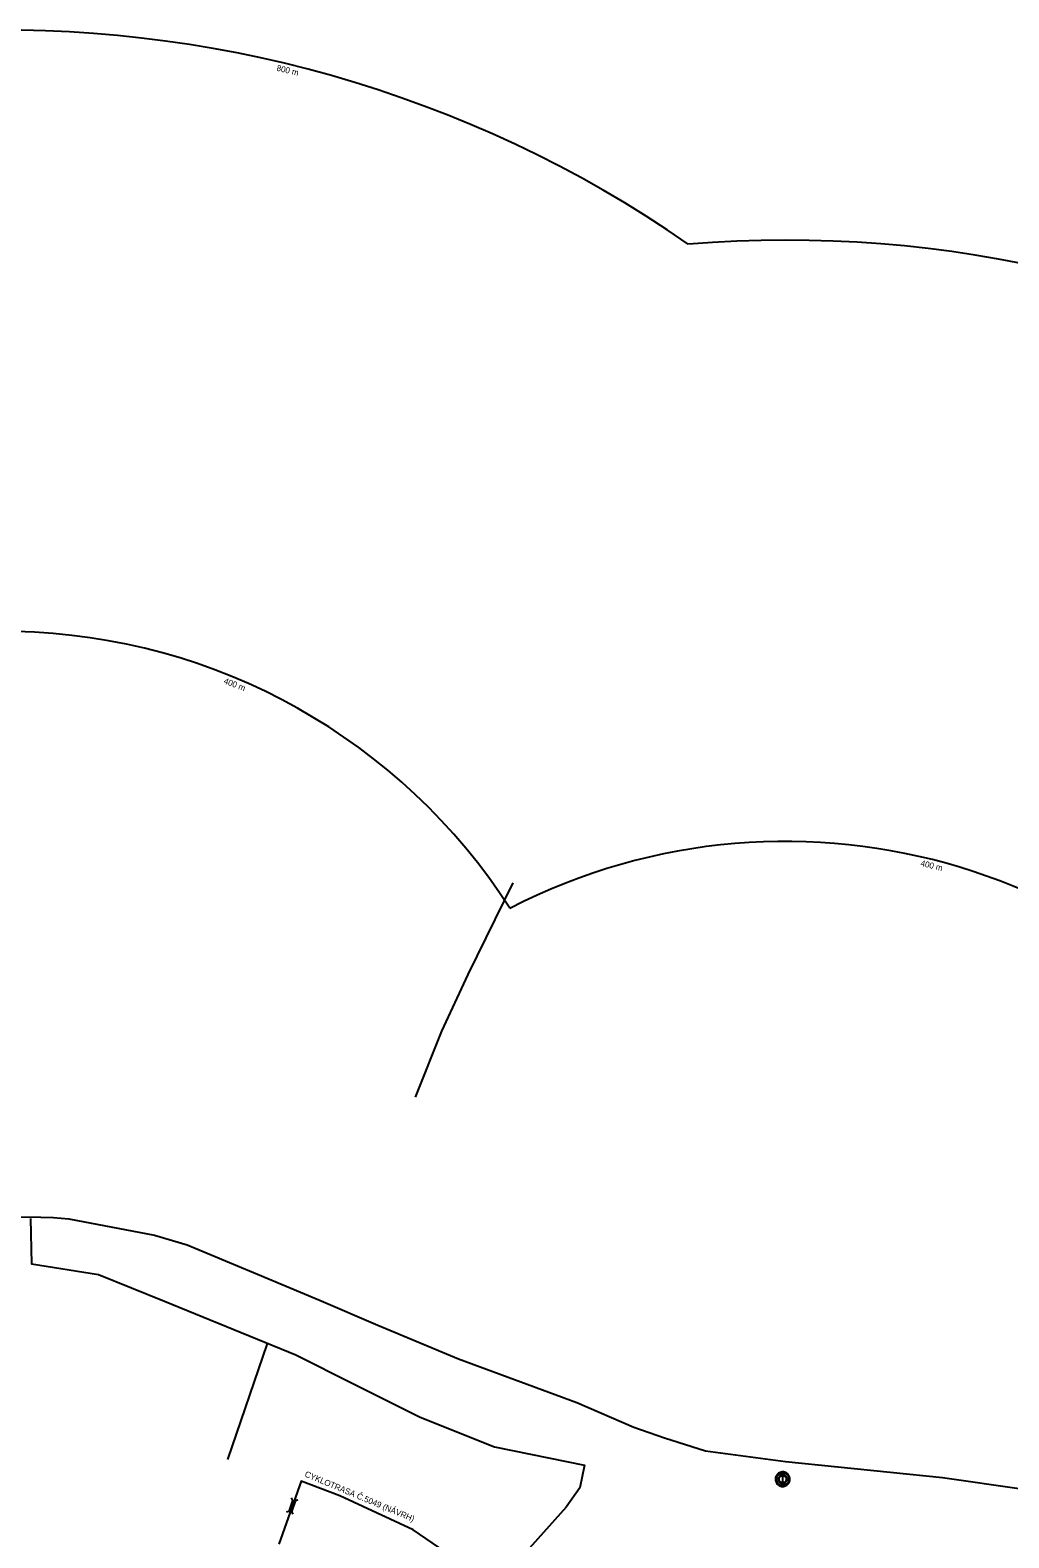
# Model space of a CAD drawing. Extents: x -520790 to -517278, y -1190021 to -1185077.
# Drawn here: x -518752 to -518101, y -1187379 to -1186376 of the extents above; entities that cross this region are included whole.
import ezdxf

# ---------------------------------------------------------------- set-up
doc = ezdxf.new("R2010")
doc.units = 0
for name, color, linetype in [('cyklostezka_n', 7, 'Continuous'), ('cyklostezka_s', 7, 'Continuous'), ('dostupnost_s', 7, 'Continuous'), ('most_s', 7, 'Continuous'), ('stezka_s', 7, 'Continuous'), ('zast_HD_s', 7, 'Continuous')]:
    doc.layers.add(name, color=color, linetype=linetype)

msp = doc.modelspace()

# ---------------------------------------------------------------- linework, layer by layer
at = {"layer": 'cyklostezka_n'}
msp.add_lwpolyline([(-518752, -1187166.7), (-518751.3, -1187196.7), (-518706.9, -1187203.8), (-518663, -1187221.6), (-518575.5, -1187257.3), (-518537.2, -1187276.5), (-518492.8, -1187298.7), (-518443.4, -1187318.5), (-518383.7, -1187330.7), (-518386.8, -1187345.7), (-518395.9, -1187358.7), (-518442.8, -1187411.1), (-518497.5, -1187373.7), (-518546.3, -1187351.1), (-518572.1, -1187341.3), (-518587, -1187383.2)], dxfattribs=at)
at = {"layer": 'cyklostezka_s'}
msp.add_lwpolyline([(-518758.6, -1187165.5), (-518745.3, -1187165.7), (-518736.7, -1187165.9), (-518726.5, -1187166.8), (-518669.5, -1187177.6), (-518647.9, -1187184.2), (-518603.7, -1187202.5), (-518560.3, -1187220.6), (-518521, -1187237.6), (-518467.4, -1187259.9), (-518388.7, -1187289), (-518350.8, -1187305.5), (-518330.4, -1187312.4), (-518303.1, -1187321.2), (-518249.9, -1187328.2), (-518145.5, -1187338.9), (-518093, -1187346.5)], dxfattribs=at)
at = {"layer": 'dostupnost_s'}
for centre, radius, start, end in [((-518770, -1187176.1), 800, 55.3007, 129.8841), ((-518249.8, -1187315.8), 800, 238.9173, 94.6412), ((-518770, -1187176.1), 400, 32.6563, 144.9976), ((-518249.8, -1187315.8), 400, 212.6563, 117.2847)]:
    msp.add_arc(centre, radius, start, end, dxfattribs=at)
at = {"layer": 'most_s'}
for points in [[(-518578.7, -1187352.5), (-518577.8, -1187354.2), (-518580.3, -1187361.4), (-518581.9, -1187361.9)], [(-518574.3, -1187353.8), (-518576, -1187354.6), (-518578.5, -1187361.8), (-518577.6, -1187363.2)]]:
    msp.add_lwpolyline(points, dxfattribs=at)
at = {"layer": 'stezka_s'}
for points in [[(-518496, -1187085.9), (-518478.5, -1187041.9), (-518461, -1187004.2), (-518431, -1186943.2)], [(-518594.6, -1187249.8), (-518621.1, -1187326.8)]]:
    msp.add_lwpolyline(points, dxfattribs=at)
at = {"layer": 'zast_HD_s'}
msp.add_line((-518251.6, -1187342.9), (-518251.6, -1187342.9), dxfattribs=at)
for points in [[(-518251.8, -1187335.2), (-518252.2, -1187335.2), (-518252.8, -1187335.3), (-518253.4, -1187335.5), (-518254, -1187335.7), (-518254.5, -1187336), (-518255, -1187336.4), (-518255.4, -1187336.8), (-518255.8, -1187337.3), (-518256.1, -1187337.8), (-518256.3, -1187338.4), (-518256.5, -1187338.9), (-518256.6, -1187339.5), (-518256.6, -1187340.2), (-518256.6, -1187340.8), (-518256.4, -1187341.3), (-518256.2, -1187341.9), (-518255.9, -1187342.5), (-518255.6, -1187343), (-518255.2, -1187343.4), (-518254.7, -1187343.8), (-518254.2, -1187344.2), (-518253.7, -1187344.4), (-518253.1, -1187344.6), (-518252.5, -1187344.8), (-518251.9, -1187344.8), (-518251.3, -1187344.8), (-518250.7, -1187344.7), (-518250.1, -1187344.5), (-518249.6, -1187344.3), (-518249.1, -1187343.9), (-518248.6, -1187343.6), (-518248.2, -1187343.1), (-518247.8, -1187342.6), (-518247.5, -1187342.1), (-518247.3, -1187341.5), (-518247.1, -1187341), (-518247, -1187340.4), (-518247, -1187339.8), (-518247.1, -1187339.1), (-518247.2, -1187338.6), (-518247.4, -1187338), (-518247.7, -1187337.5), (-518248.1, -1187337), (-518248.5, -1187336.5), (-518249, -1187336.1), (-518249.5, -1187335.8), (-518250, -1187335.5), (-518250.6, -1187335.4), (-518251.2, -1187335.2), (-518251.8, -1187335.2)], [(-518247.5, -1187340), (-518247.5, -1187339.5), (-518247.6, -1187338.9), (-518247.8, -1187338.4), (-518248, -1187337.9), (-518248.3, -1187337.4), (-518248.7, -1187337), (-518249.1, -1187336.7), (-518249.5, -1187336.3), (-518250, -1187336.1), (-518250.5, -1187335.9), (-518251, -1187335.7), (-518251.6, -1187335.7), (-518252.1, -1187335.7), (-518252.7, -1187335.8), (-518253.2, -1187335.9), (-518253.7, -1187336.1), (-518254.2, -1187336.4), (-518254.6, -1187336.7), (-518255, -1187337.1), (-518255.3, -1187337.5), (-518255.6, -1187338), (-518255.9, -1187338.5), (-518256, -1187339), (-518256.1, -1187339.5), (-518256.1, -1187340.1), (-518256.1, -1187340.6), (-518256, -1187341.2), (-518255.8, -1187341.7), (-518255.5, -1187342.2), (-518255.2, -1187342.6), (-518254.9, -1187343), (-518254.5, -1187343.4), (-518254, -1187343.7), (-518253.5, -1187344), (-518253, -1187344.2), (-518252.5, -1187344.3), (-518251.9, -1187344.3), (-518251.4, -1187344.3), (-518250.9, -1187344.2), (-518250.3, -1187344.1), (-518249.8, -1187343.8), (-518249.4, -1187343.6), (-518248.9, -1187343.2), (-518248.5, -1187342.8), (-518248.2, -1187342.4), (-518247.9, -1187341.9), (-518247.7, -1187341.4), (-518247.6, -1187340.9), (-518247.5, -1187340.4), (-518247.5, -1187340)], [(-518251.8, -1187335.7), (-518251.4, -1187335.7), (-518250.9, -1187335.8), (-518250.4, -1187335.9), (-518249.9, -1187336.1), (-518249.4, -1187336.4), (-518249, -1187336.7), (-518248.6, -1187337.1), (-518248.2, -1187337.6), (-518248, -1187338), (-518247.7, -1187338.5), (-518247.6, -1187339), (-518247.5, -1187339.6), (-518247.5, -1187340.1), (-518247.5, -1187340.7), (-518247.7, -1187341.2), (-518247.8, -1187341.7), (-518248.1, -1187342.2), (-518248.4, -1187342.7), (-518248.8, -1187343.1), (-518249.2, -1187343.4), (-518249.6, -1187343.7), (-518250.1, -1187344), (-518250.6, -1187344.2), (-518251.2, -1187344.3), (-518251.7, -1187344.3), (-518252.3, -1187344.3), (-518252.8, -1187344.2), (-518253.3, -1187344.1), (-518253.8, -1187343.8), (-518254.3, -1187343.5), (-518254.7, -1187343.2), (-518255.1, -1187342.8), (-518255.4, -1187342.4), (-518255.7, -1187341.9), (-518255.9, -1187341.4), (-518256, -1187340.9), (-518256.1, -1187340.3), (-518256.1, -1187339.8), (-518256.1, -1187339.2), (-518255.9, -1187338.7), (-518255.7, -1187338.2), (-518255.5, -1187337.7), (-518255.2, -1187337.3), (-518254.8, -1187336.9), (-518254.4, -1187336.5), (-518253.9, -1187336.2), (-518253.4, -1187336), (-518252.9, -1187335.8), (-518252.4, -1187335.7), (-518251.8, -1187335.7)], [(-518252.1, -1187337.1), (-518252.4, -1187337.2), (-518252.8, -1187337.3), (-518253.1, -1187337.4), (-518253.4, -1187337.6), (-518253.7, -1187337.8), (-518254, -1187338.1), (-518254.2, -1187338.4), (-518254.4, -1187338.7), (-518254.5, -1187339), (-518254.6, -1187339.4), (-518254.7, -1187339.7), (-518254.7, -1187340.1), (-518254.6, -1187340.5), (-518254.6, -1187340.8), (-518254.4, -1187341.2), (-518254.3, -1187341.5), (-518254.1, -1187341.8), (-518253.8, -1187342.1), (-518253.5, -1187342.3), (-518253.2, -1187342.5), (-518252.9, -1187342.7), (-518252.6, -1187342.8), (-518252.2, -1187342.8), (-518251.9, -1187342.9), (-518251.6, -1187342.9)], [(-518252, -1187342.4), (-518252.3, -1187342.4), (-518252.6, -1187342.3), (-518252.9, -1187342.1), (-518253.2, -1187342), (-518253.4, -1187341.8), (-518253.6, -1187341.6), (-518253.8, -1187341.3), (-518254, -1187341.1), (-518254.1, -1187340.8), (-518254.2, -1187340.5), (-518254.2, -1187340.2), (-518254.2, -1187339.9), (-518254.2, -1187339.6), (-518254.1, -1187339.3), (-518254, -1187339), (-518253.9, -1187338.7), (-518253.7, -1187338.5), (-518253.5, -1187338.3), (-518253.3, -1187338.1), (-518253, -1187337.9), (-518252.7, -1187337.8), (-518252.4, -1187337.7), (-518252.1, -1187337.6), (-518252.1, -1187337.6)], [(-518252.1, -1187337.6), (-518252.1, -1187337.1)], [(-518251.6, -1187342.9), (-518251.2, -1187342.8), (-518250.8, -1187342.7), (-518250.5, -1187342.6), (-518250.2, -1187342.4), (-518249.9, -1187342.2), (-518249.7, -1187341.9), (-518249.4, -1187341.6), (-518249.2, -1187341.3), (-518249.1, -1187341), (-518249, -1187340.6), (-518248.9, -1187340.3), (-518248.9, -1187339.9), (-518249, -1187339.5), (-518249, -1187339.2), (-518249.2, -1187338.8), (-518249.3, -1187338.5), (-518249.5, -1187338.2), (-518249.8, -1187338), (-518250.1, -1187337.7), (-518250.4, -1187337.5), (-518250.7, -1187337.4), (-518251, -1187337.2), (-518251.4, -1187337.2), (-518251.8, -1187337.1), (-518252, -1187337.1)], [(-518252, -1187337.1), (-518252, -1187342.4)], [(-518251.8, -1187335.2), (-518251.8, -1187335.7)], [(-518251.8, -1187335.7), (-518251.8, -1187335.2)], [(-518251.6, -1187342.9), (-518251.6, -1187337.6)], [(-518251.6, -1187337.6), (-518251.3, -1187337.6), (-518251, -1187337.7), (-518250.7, -1187337.9), (-518250.4, -1187338), (-518250.2, -1187338.2), (-518250, -1187338.4), (-518249.8, -1187338.7), (-518249.6, -1187338.9), (-518249.5, -1187339.2), (-518249.4, -1187339.5), (-518249.4, -1187339.8), (-518249.4, -1187340.1), (-518249.4, -1187340.4), (-518249.5, -1187340.7), (-518249.6, -1187341), (-518249.7, -1187341.3), (-518249.9, -1187341.5), (-518250.1, -1187341.7), (-518250.4, -1187341.9), (-518250.6, -1187342.1), (-518250.9, -1187342.2), (-518251.2, -1187342.3), (-518251.5, -1187342.4), (-518251.6, -1187342.4)], [(-518251.6, -1187342.4), (-518251.6, -1187342.9)]]:
    msp.add_lwpolyline(points, dxfattribs=at)

# ---------------------------------------------------------------- texts
at = {"layer": 'cyklostezka_n'}
msp.add_text('CYKLOTRASA Č.5049 (NÁVRH)', height=4, rotation=337.2199, dxfattribs=at).set_placement((-518570.1, -1187338.1))
at = {"layer": 'dostupnost_s'}
for s, rotation, p in [('800 m', 346.4234, (-518588.7, -1186403)), ('400 m', 338.7751, (-518623.9, -1186810.5)), ('400 m', 346.4234, (-518160.4, -1186932))]:
    msp.add_text(s, height=4, rotation=rotation, dxfattribs=at).set_placement(p)

doc.saveas('drawing.dxf')
